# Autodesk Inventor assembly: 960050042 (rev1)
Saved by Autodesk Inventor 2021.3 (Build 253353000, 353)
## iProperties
Created: 2023-03
Part Number: 960050042 (rev1)
Document SubType Name: Assembly
Designer: AdminForWorker
Title: 960050042 (rev1) v2
Author: AdminForWorker
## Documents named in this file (2)
- z:\worker\convert-fusion-r08-cosv3\tmp\job-1\3553\output\files\82b4d9ad-b575-4129-b9ca-4964d6b72adf\960050042 (rev1) v2_2.iam
- z:\worker\convert-fusion-r08-cosv3\tmp\job-1\3553\output\files\82b4d9ad-b575-4129-b9ca-4964d6b72adf\960050042 (rev1).ipt
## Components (1 placed, 1 different names)
1. 960050042 (rev1):1
